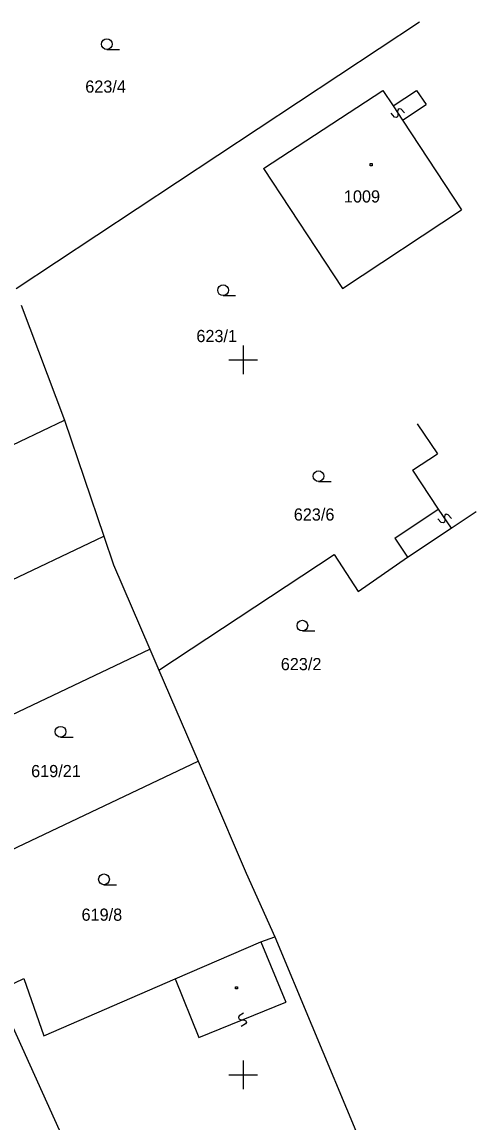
# Model space of a CAD drawing. Extents: x -493648 to -493033, y -1127718 to -1127026.
# Drawn here: x -493065.5 to -493033.7, y -1127103.3 to -1127026.4 of the extents above; entities that cross this region are included whole.
import ezdxf

# ---------------------------------------------------------------- set-up
doc = ezdxf.new("R2010")
doc.units = 0
doc.layers.add('katastrální mapa', color=7, linetype='Continuous')
doc.layers.add('síť', color=7, linetype='Continuous')

msp = doc.modelspace()

# ---------------------------------------------------------------- linework, layer by layer
at = {"layer": 'katastrální mapa'}
for p, q in [((-493065.9, -1127045.01), (-493037.66, -1127026.38)), ((-493059.55, -1127028.3), (-493058.67, -1127028.3)), ((-493048.57, -1127036.62), (-493040.22, -1127031.18)), ((-493040.22, -1127031.18), (-493039.51, -1127032.25)), ((-493039.51, -1127032.25), (-493037.86, -1127031.16)), ((-493037.86, -1127031.16), (-493037.2, -1127032.16)), ((-493039.51, -1127032.25), (-493038.85, -1127033.25)), ((-493039.08, -1127032.45), (-493039.16, -1127032.5)), ((-493038.94, -1127032.47), (-493039.08, -1127032.45)), ((-493038.71, -1127032.74), (-493038.94, -1127032.47)), ((-493038.85, -1127033.25), (-493037.2, -1127032.16)), ((-493039.42, -1127033.03), (-493039.65, -1127032.76)), ((-493039.28, -1127033.05), (-493039.42, -1127033.03)), ((-493039.2, -1127033), (-493039.28, -1127033.05)), ((-493039.17, -1127032.86), (-493039.2, -1127033)), ((-493039.16, -1127032.5), (-493039.19, -1127032.64)), ((-493039.19, -1127032.64), (-493039.17, -1127032.86)), ((-493038.85, -1127033.25), (-493034.71, -1127039.51)), ((-493041.12, -1127036.28), (-493040.97, -1127036.28)), ((-493041.12, -1127036.43), (-493041.12, -1127036.28)), ((-493040.97, -1127036.28), (-493040.97, -1127036.43)), ((-493048.57, -1127036.62), (-493043.06, -1127045.02)), ((-493040.97, -1127036.43), (-493041.12, -1127036.43)), ((-493043.06, -1127045.02), (-493034.71, -1127039.51)), ((-493051.41, -1127045.51), (-493050.53, -1127045.51)), ((-493065.54, -1127046.19), (-493062.51, -1127054.22)), ((-493079.77, -1127062.39), (-493062.51, -1127054.22)), ((-493062.51, -1127054.22), (-493059.75, -1127062.34)), ((-493037.82, -1127054.47), (-493036.4, -1127056.58)), ((-493038.15, -1127057.71), (-493036.4, -1127056.58)), ((-493038.15, -1127057.71), (-493036.34, -1127060.44)), ((-493044.73, -1127058.51), (-493043.85, -1127058.51)), ((-493039.38, -1127062.46), (-493036.34, -1127060.44)), ((-493036.34, -1127060.44), (-493035.45, -1127061.77)), ((-493035.88, -1127060.86), (-493035.91, -1127060.99)), ((-493035.8, -1127060.8), (-493035.88, -1127060.86)), ((-493035.66, -1127060.83), (-493035.8, -1127060.8)), ((-493035.42, -1127061.09), (-493035.66, -1127060.83)), ((-493035.45, -1127061.77), (-493033.7, -1127060.61)), ((-493036.13, -1127061.38), (-493036.37, -1127061.12)), ((-493035.99, -1127061.41), (-493036.13, -1127061.38)), ((-493035.91, -1127061.35), (-493035.99, -1127061.41)), ((-493035.91, -1127060.99), (-493035.88, -1127061.22)), ((-493035.88, -1127061.22), (-493035.91, -1127061.35)), ((-493076.17, -1127070.11), (-493059.75, -1127062.34)), ((-493059.75, -1127062.34), (-493059.08, -1127064.33)), ((-493039.38, -1127062.46), (-493038.49, -1127063.79)), ((-493038.49, -1127063.79), (-493035.45, -1127061.77)), ((-493055.9, -1127071.71), (-493043.64, -1127063.61)), ((-493043.64, -1127063.61), (-493041.96, -1127066.19)), ((-493041.96, -1127066.19), (-493038.49, -1127063.79)), ((-493059.08, -1127064.33), (-493056.53, -1127070.24)), ((-493045.86, -1127068.96), (-493044.98, -1127068.96)), ((-493072.58, -1127077.83), (-493056.53, -1127070.24)), ((-493056.53, -1127070.24), (-493055.9, -1127071.71)), ((-493055.9, -1127071.71), (-493053.16, -1127078.07)), ((-493062.79, -1127076.38), (-493061.91, -1127076.38)), ((-493068.17, -1127085.17), (-493053.16, -1127078.07)), ((-493053.16, -1127078.07), (-493052.3, -1127080.06)), ((-493052.3, -1127080.06), (-493049.79, -1127085.89)), ((-493049.79, -1127085.89), (-493047.78, -1127090.34)), ((-493059.75, -1127086.7), (-493058.87, -1127086.7)), ((-493054.77, -1127093.29), (-493048.76, -1127090.7)), ((-493048.76, -1127090.7), (-493047.78, -1127090.34)), ((-493048.76, -1127090.7), (-493047.02, -1127094.92)), ((-493047.78, -1127090.34), (-493045.2, -1127096.54)), ((-493067.27, -1127094.16), (-493065.36, -1127093.25)), ((-493065.36, -1127093.25), (-493063.97, -1127097.26)), ((-493063.97, -1127097.26), (-493054.77, -1127093.29)), ((-493054.77, -1127093.29), (-493053.1, -1127097.38)), ((-493050.54, -1127093.84), (-493050.39, -1127093.84)), ((-493050.54, -1127093.99), (-493050.54, -1127093.84)), ((-493050.39, -1127093.99), (-493050.54, -1127093.99)), ((-493050.39, -1127093.84), (-493050.39, -1127093.99)), ((-493067.27, -1127094.16), (-493051.77, -1127128.35)), ((-493053.1, -1127097.38), (-493047.02, -1127094.92)), ((-493050.28, -1127095.86), (-493050.34, -1127095.99)), ((-493050.34, -1127095.99), (-493050.3, -1127096.09)), ((-493050.3, -1127096.09), (-493050.17, -1127096.14)), ((-493049.98, -1127095.69), (-493050.28, -1127095.86)), ((-493050.17, -1127096.14), (-493049.95, -1127096.16)), ((-493049.95, -1127096.16), (-493049.82, -1127096.21)), ((-493049.78, -1127096.31), (-493049.84, -1127096.44)), ((-493049.82, -1127096.21), (-493049.78, -1127096.31)), ((-493049.84, -1127096.44), (-493050.14, -1127096.61)), ((-493045.2, -1127096.54), (-493042.01, -1127104.2))]:
    msp.add_line(p, q, dxfattribs=at)
for centre in [(-493059.55, -1127027.925), (-493051.41, -1127045.135), (-493044.73, -1127058.135), (-493045.86, -1127068.585), (-493062.79, -1127076.005), (-493059.75, -1127086.325)]:
    msp.add_circle(centre, 0.375, dxfattribs=at)
at = {"layer": 'síť'}
for p, q in [((-493050, -1127049), (-493050, -1127051)), ((-493051, -1127050), (-493049, -1127050)), ((-493050, -1127099), (-493050, -1127101)), ((-493051, -1127100), (-493049, -1127100))]:
    msp.add_line(p, q, dxfattribs=at)

# ---------------------------------------------------------------- texts
at = {"layer": 'katastrální mapa'}
for s, p in [('623/4', (-493061.06, -1127031.32)), ('1009', (-493042.95, -1127039)), ('623/1', (-493053.28, -1127048.76)), ('623/6', (-493046.46, -1127061.24)), ('623/2', (-493047.37, -1127071.7)), ('619/21', (-493064.85, -1127079.18)), ('619/8', (-493061.32, -1127089.22))]:
    msp.add_text(s, height=0.849996, dxfattribs=at).set_placement(p)

doc.saveas('drawing.dxf')
